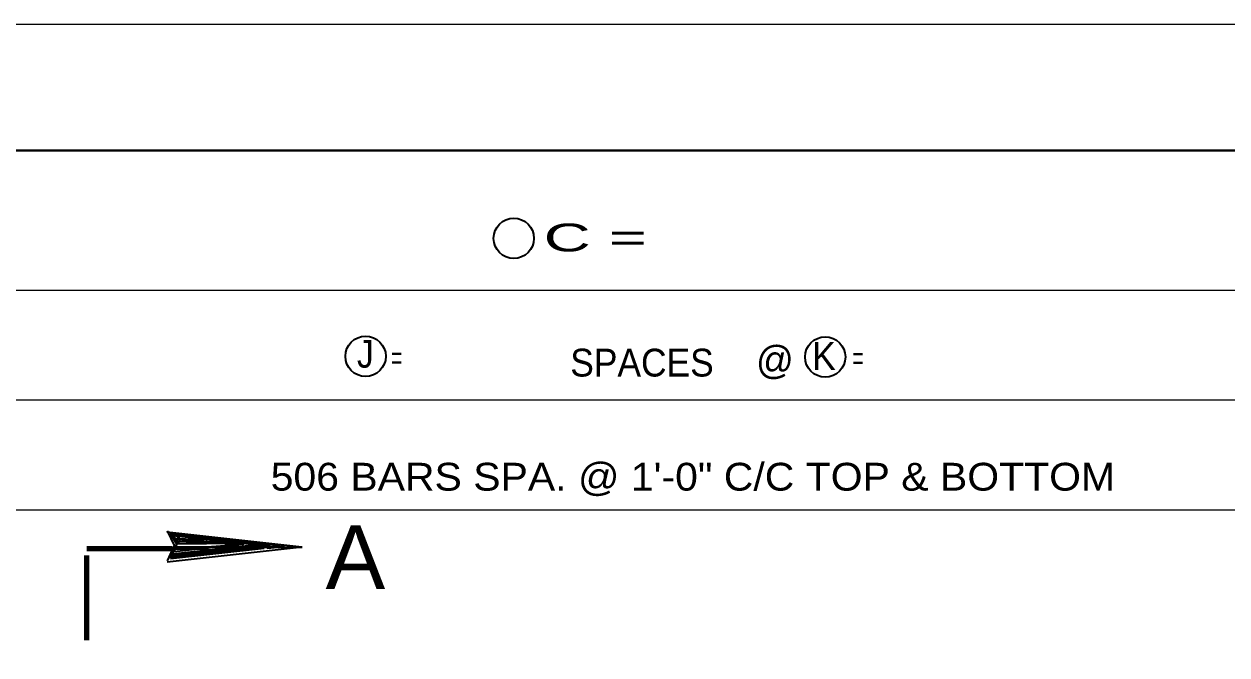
# Model space of a CAD drawing. Extents: x 144 to 252, y 360 to 425.
# Drawn here: x 160.77 to 174.95, y 418.04 to 425.48 of the extents above; entities that cross this region are included whole.
import ezdxf
from ezdxf.enums import TextEntityAlignment as Align

# ---------------------------------------------------------------- set-up
doc = ezdxf.new("R2010")
doc.units = 0
doc.header["$LTSCALE"] = 0.13
for name, color, linetype, lineweight in [('1', 7, 'Continuous', 40), ('16', 7, 'Continuous', 13), ('3', 7, 'Continuous', 13)]:
    doc.layers.add(name, color=color, linetype=linetype, lineweight=lineweight)

msp = doc.modelspace()

# ---------------------------------------------------------------- linework, layer by layer
at = {"layer": '1', "lineweight": 13}
for p, q in [((143.8112, 425.4823), (251.8112, 425.4823)), ((177.7937, 419.7488), (157.751, 419.7488))]:
    msp.add_line(p, q, dxfattribs=at)
at = {"layer": '1', "lineweight": 35}
for p, q in [((162.4561, 419.4957), (164.0461, 419.3187)), ((162.4921, 419.4537), (163.6741, 419.3247)), ((162.4951, 419.4807), (163.6801, 419.3517)), ((162.4951, 419.4747), (163.6801, 419.3487)), ((162.4951, 419.4687), (163.6741, 419.3367)), ((162.4981, 419.4867), (163.6801, 419.3577)), ((164.0491, 419.3157), (162.4591, 419.1387)), ((162.4591, 419.3127), (164.0491, 419.3127)), ((162.4891, 419.2317), (163.5931, 419.3517)), ((162.4921, 419.2137), (163.5931, 419.3337)), ((162.4951, 419.1957), (163.5991, 419.3157)), ((162.4981, 419.1807), (163.6021, 419.3007))]:
    msp.add_line(p, q, dxfattribs=at)
at = {"layer": '1'}
msp.add_lwpolyline([(250.3172, 361.9183), (250.3172, 423.9913), (149.8112, 423.9913), (149.8112, 361.9183), (230.3642, 361.9183)], dxfattribs=at)
at = {"layer": '1', "lineweight": 35}
for points in [[(162.4621, 419.1537), (162.5461, 419.3337), (162.4621, 419.5077)], [(162.5701, 419.3517), (163.2781, 419.3607), (163.2751, 419.3427), (163.1371, 419.3517), (162.5701, 419.3607), (163.0261, 419.3757), (162.5491, 419.3847), (162.8851, 419.3967), (162.5371, 419.4147), (163.0801, 419.3727), (163.7881, 419.3427), (163.6411, 419.3037), (163.8361, 419.3217), (162.5701, 419.3157), (162.9391, 419.2917), (162.5491, 419.2917), (163.3591, 419.3487), (162.5431, 419.2587), (162.5731, 419.3487), (162.5071, 419.4597), (162.5431, 419.4357), (162.5731, 419.3727), (162.6151, 419.3907), (162.5881, 419.4417), (162.5641, 419.3277), (162.5311, 419.2587), (162.4981, 419.1807)]]:
    msp.add_lwpolyline(points, dxfattribs=at)
for centre in [(166.5451, 422.9552), (164.7979, 421.5642), (170.2151, 421.5567)]:
    msp.add_circle(centre, 0.238, dxfattribs=at)
at = {"layer": '16', "lineweight": 106}
for p, q in [((161.5143, 419.2987), (162.5143, 419.2987)), ((161.5143, 418.2154), (161.5143, 419.2154))]:
    msp.add_line(p, q, dxfattribs=at)
at = {"layer": '3'}
for p, q in [((156.7562, 422.3458), (180.7569, 422.3458)), ((156.7571, 421.0507), (179.4617, 421.0507))]:
    msp.add_line(p, q, dxfattribs=at)

# ---------------------------------------------------------------- texts
at = {"layer": '1'}
for s, height, width, p in [('J', 0.3281, 0.9, (164.7954, 421.4296)), ('K', 0.3281, 0.95, (170.2004, 421.4035)), ('=', 0.2833, 0.6, (165.1634, 421.4069)), ('=', 0.2833, 0.6, (170.6022, 421.4033))]:
    msp.add_text(s, height=height, dxfattribs=dict(at, width=width)).set_placement(p, align=Align.CENTER)
at = {"layer": '1', "width": 0.95}
msp.add_text('SPACES', height=0.3281, dxfattribs=at).set_placement((167.2106, 421.326))
at = {"layer": '1'}
msp.add_text('@', height=0.3281, dxfattribs=at).set_placement((169.6227, 421.3586), align=Align.CENTER)
at = {"layer": '16', "width": 1.75}
msp.add_text('C =      ', height=0.3281, dxfattribs=at).set_placement((168.1453, 422.8012), align=Align.CENTER)
at = {"layer": '16'}
for s, height, width, p in [('506 BARS SPA. @ 1\'-0" C/C TOP & BOTTOM', 0.3281, 1.1, (163.6795, 419.9806)), ('A', 0.75, 1.05, (164.327, 418.821))]:
    msp.add_text(s, height=height, dxfattribs=dict(at, width=width)).set_placement(p)

doc.saveas('drawing.dxf')
